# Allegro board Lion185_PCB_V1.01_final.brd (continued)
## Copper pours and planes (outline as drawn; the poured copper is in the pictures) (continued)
+VGFX on BOTTOM (solid shape): 83.86,87.98 84.45,87.98 84.73,87.7 85.2,87.7 85.2,87.69 85.22,87.69 85.22,87.63 85.93,87.63 85.93,87.69 85.96,87.69 85.96,87.7 87.39,87.7 87.41,87.69 87.43,87.68 87.55,87.57 87.56,87.55 87.56,87.52 87.56,87.37 87.56,87.34 87.55,87.32 87.36,87.13 87.36,86.65 87.24,86.52 86.72,86.52 86.61,86.63 86.61,87.03 86.58,87.07 86.35,87.07 86.35,87.18 85.6,87.18 85.6,87.18 84.78,87.18 84.78,86.99 84.74,86.94 84.74,86.84 84.65,86.75 84.65,86.57 83.76,86.57 83.76,86.5 83.74,86.45 83.64,86.43 83.64,86.32 83.63,86.32 83.63,85.55 83.64,85.55 83.64,83.46 83.62,83.42 83.58,83.4 83.19,83.4 83.14,83.42 83.12,83.46 83.12,84.65 83.13,84.65 83.13,85.42 83.12,85.42 83.12,86.13 82.9,86.35 82.88,86.4 82.89,86.44 82.9,86.92 82.43,87.03 82.4,87.02 82.36,87.04 82.34,87.08 82.34,87.63 83.02,88.31 83.52,88.31
+VGFX on LAY5 (solid shape): outline of 4668 points within 77.47,83.29 93.4,123.11
+VSDIO on BOTTOM (solid shape): 68.91,87.36 72.99,87.36 73,87.33 73.29,87.12 73.63,87.24 73.7,87.27 73.78,87.24 74.64,86.38 74.85,86.38 74.86,86.35 75.07,86.15 75.35,86.15 75.36,86.15 75.77,86.15 75.78,86.15 75.92,86.12 76.06,86.15 76.07,86.15 76.12,86.15 76.12,86.17 76.16,86.21 76.22,86.26 76.25,86.27 76.31,86.27 76.31,86.15 76.49,86.15 76.49,86.15 76.63,86.12 76.77,86.15 76.78,86.15 77.07,86.15 77.2,86.15 77.21,86.15 77.43,86.13 77.63,86.24 77.7,86.28 78.06,86.12 78.41,86.28 78.77,86.12 79.12,86.28 79.2,86.24 79.41,86.13 79.65,86.16 79.66,86.17 80.01,86.17 80.02,86.16 80.25,86.13 80.46,86.23 80.6,86.09 81.29,86.09 81.59,86.38 81.59,86.38 81.77,86.31 81.97,86.34 82,86.35 82.08,86.27 82.08,85.87 81.88,85.68 74.73,85.68 73.76,86.65 68.73,86.65 64.48,90.9 62.1,90.9 62.01,90.99 62.01,91.36 62.11,91.46 64.82,91.46
+VSFR on BOTTOM (solid shape): 87.7,118.77 87.7,118.01 87.53,117.85 87.53,116.13 87.41,116 86.78,116 86.61,116.17 86.61,118.74 86.69,118.83 87.64,118.83
+VSFR on LAY3 (solid shape): outline of 958 points within 84.7,81.13 93.36,106.21
+VSFR on LAY4 (solid shape): 89.21,106.54 89.21,105.76 88.2,104.75 88.2,102.42 86.68,100.89 86.68,97.67 86.3,97.29 86.3,90.78 86.14,90.45 86.34,90.14 86.39,90.07 86.37,89.98 85.06,88.68 84.88,88.68 84.55,89 84.54,89.06 84.52,89.12 84.52,89.56 84.52,89.57 84.55,89.72 84.52,89.87 84.52,89.88 84.52,90.11 84.62,90.21 84.65,90.22 84.69,90.21 85.15,90.15 85.33,90.58 85.33,98.28 85.62,98.58 86.1,98.81 85.9,99.29 85.87,99.31 85.87,101.16 87.12,102.42 87.12,105.24 88.56,106.67 89.08,106.67
+VSM on TOP (solid shape): 67.38,74.01 67.38,69.81 67.16,69.59 44.66,69.59 44.49,69.76 44.49,70.98 61.49,70.98 61.5,70.92 61.51,70.87 61.54,70.82 61.57,70.77 61.6,70.73 61.64,70.69 61.69,70.66 61.74,70.64 61.79,70.62 61.85,70.61 61.9,70.61 61.96,70.62 62.01,70.64 62.06,70.66 62.1,70.69 62.15,70.73 62.18,70.77 62.21,70.82 62.23,70.87 62.25,70.92 62.25,70.98 62.25,71.03 62.24,71.09 62.22,71.14 62.2,71.19 62.16,71.23 62.13,71.27 62.08,71.31 62.03,71.33 61.98,71.35 61.93,71.36 61.87,71.37 61.82,71.36 61.76,71.35 61.71,71.33 61.66,71.31 61.62,71.27 61.58,71.23 61.55,71.19 61.52,71.14 61.51,71.09 61.5,71.03 61.49,70.98 44.49,70.98 44.49,74.57 44.49,74.89 45.19,75.59 65.8,75.59
+VSM on TOP (solid shape): 99.58,59.8 99.58,59.72 99.57,59.7 99.54,59.29 99.89,59.09 99.91,59.09 100.17,58.83 100.17,58.53 100.15,58.53 100.15,58.5 100.08,58.5 100.08,57.58 99.67,57.58 99.67,58.5 99.6,58.5 99.6,58.53 98.35,58.53 98.35,58.5 98.28,58.5 98.28,57.58 97.87,57.58 97.87,58.5 97.8,58.5 97.8,58.53 97.72,58.53 97.72,58.77 98.04,59.09 98.06,59.09 98.42,59.3 98.36,59.72 98.36,59.73 98.34,59.77 98.49,59.93 99.46,59.93
+VSM on BOTTOM (solid shape): 98.31,58.83 98.31,58.54 97.9,58.13 96.77,58.13 96.32,58.58 96.32,58.88 96.47,59.02 98.12,59.02
+VSM on BOTTOM (solid shape): 88.72,58.99 89.12,58.99 89.29,58.82 89.29,58.45 89.07,58.23 87.22,58.23 87.04,58.42 87.04,58.85 87.17,58.99 87.57,58.99 87.77,59.19 88.51,59.19
+VSM on BOTTOM (solid shape): 89.28,56.11 89.28,55.88 89.09,55.69 88.66,55.69 88.49,55.52 87.84,55.52 87.63,55.73 87.18,55.73 87.05,55.86 87.05,56.1 87.24,56.29 89.1,56.29
+VSM on BOTTOM (solid shape): 98.32,56.13 98.32,55.88 98.15,55.7 97.75,55.7 97.55,55.5 96.79,55.5 96.6,55.69 96.22,55.69 96.08,55.84 96.08,56.12 96.39,56.43 98.02,56.43
+VSM on BOTTOM (solid shape): 87.69,121.9 87.69,120.24 87.62,120.17 86.28,120.17 86.12,120.01 86.02,120.01 85.76,120.27 85.76,121.83 85.94,122 87.6,122
+VSM on BOTTOM (solid shape): 129.45,55.14 129.45,51.3 129.12,50.97 127.61,50.97 126.87,51.71 126.87,51.78 128.16,53.08 128.16,55.14 128.23,55.21 129.38,55.21
+VSM on BOTTOM (solid shape): 90.49,59.58 90.49,59.27 90.67,59.09 91.12,59.09 91.31,59.28 92.19,59.28 92.41,59.05 93.1,59.05 93.24,59.19 93.96,59.19 94.1,59.05 94.58,59.05 94.72,58.91 94.72,58.61 94.43,58.32 90.47,58.32 89.81,58.98 89.81,59.59 89.92,59.71 90.37,59.71
+VSM on BOTTOM (solid shape): 101.69,53.54 101.69,50.12 101.38,49.81 88.53,49.81 87.97,50.37 85.13,50.37 84.96,50.54 84.96,50.67 85.14,50.85 85.34,50.85 85.58,51.1 85.58,51.39 85.74,51.54 86.37,51.54 86.45,51.46 86.45,51.12 86.71,50.87 87.19,50.87 87.4,51.07 87.4,51.27 87.47,51.34 88,51.34 88.46,50.88 88.97,50.88 89.28,51.19 89.95,51.19 90.33,50.81 92.72,50.81 92.82,50.9 92.82,51.14 92.92,51.24 93.57,51.24 93.96,50.86 96.18,50.86 96.28,50.86 96.37,50.95 96.37,51.28 96.46,51.37 96.99,51.37 97.52,50.85 99.73,50.85 100.12,51.23 100.5,51.23 100.94,51.67 100.94,53.51 101.13,53.7 101.53,53.7
+VSM on BOTTOM (solid shape): outline of 2522 points within 65.58,64.74 100.13,80.23
+VSM on LAY5 (solid shape): outline of 5880 points within 65.77,50.33 103.41,81.27
+VSM_VTT on BOTTOM (solid shape): 52.56,62.38 52.56,62.21 56.74,58.03 56.74,58.03 57.44,57.33 58.44,56.33 58.45,56.33 61.24,56.33 61.26,56.33 61.45,56.14 61.45,55.85 60.83,55.24 59.42,55.24 58.16,53.97 58.16,51.62 58.36,51.41 60.48,51.41 60.66,51.23 60.66,50.63 60.61,50.57 58.6,50.57 58.33,50.68 58.07,50.57 57.85,50.57 56.93,51.5 56.93,53.03 56.93,53.04 56.93,55.06 52.52,59.47 52.52,60.24 52.09,60.67 51.63,60.67 51.35,60.94 51.35,61.35 51.54,61.53 51.54,62.4 51.58,62.44 51.69,62.44 51.76,62.41 51.79,62.34 51.79,62.24 51.79,61.58 51.82,61.54 51.82,61.52 52.01,61.2 52.39,61.2 52.58,61.54 52.37,61.86 52.33,61.9 52.33,62.41 52.36,62.45 52.5,62.45
GL850_AVDD1 on BOTTOM (solid shape): 145.08,114.82 145.08,113.34 144.83,113.09 143.78,113.09 143.37,113.49 143.37,114.26 143.36,114.27 143.36,114.7 143.54,114.88 145.02,114.88
LAN_N1 on BOTTOM (solid shape): 62.78,18.95 62.78,13.55 62.53,13.3 61,13.3 60.79,13.51 60.79,18.78 61.15,19.13 62.6,19.13
LCD_VCC on TOP (solid shape): 50.56,135.33 50.56,132.12 49.95,131.51 46.52,131.51 46.28,131.27 46.28,129.55 46.16,129.43 45.17,129.43 45.17,129.42 43.29,129.42 43.05,129.66 43.05,132.35 42.94,132.46 41.73,132.46 41.6,132.59 41.6,135.5 41.91,135.81 50.08,135.81
LL1 on TOP (solid shape): outline of 112 points within 22.4,89.11 29,96.48
LL2 on TOP (solid shape): 29.19,81.66 29.19,71.4 28.71,70.91 25.37,70.91 24.37,71.91 24.37,77.16 24.37,77.16 24.37,78.84 24.37,78.84 24.37,81.33 24.86,81.82 29.03,81.82
REGOUT on BOTTOM (solid shape): 53.99,45.32 53.99,44.45 54.53,43.9 55.38,43.9 55.52,43.77 55.52,42.8 55.39,42.68 52.39,42.68 51.38,43.69 50.78,43.69 50.5,43.96 50.5,45.41 50.69,45.6 53.71,45.6
TP_VCC on TOP (solid shape): 11.47,39.74 11.47,38.42 11.2,38.15 10.55,38.15 9.98,37.58 6.52,37.58 6.4,37.7 6.4,39.18 6.58,39.37 8.19,39.37 8.82,40 11.22,40
N333289805 on TOP (solid shape): 131.61,67.88 131.61,64.73 131.49,64.6 129.35,64.6 128.93,64.19 128.93,62.87 128.77,62.71 126.02,62.71 125.54,63.19 125.54,66.7 125.86,66.7 125.86,66.65 125.88,66.6 125.9,66.55 125.93,66.5 125.96,66.46 126,66.42 126.05,66.39 126.1,66.36 126.15,66.35 126.21,66.34 126.26,66.34 126.32,66.35 126.37,66.36 126.42,66.39 126.47,66.42 126.51,66.46 126.54,66.5 126.57,66.55 126.59,66.6 126.61,66.65 126.61,66.7 126.61,66.76 126.6,66.81 126.58,66.87 126.56,66.92 126.52,66.96 126.49,67 126.44,67.03 126.39,67.06 126.34,67.08 126.29,67.09 126.23,67.1 126.18,67.09 126.12,67.08 126.07,67.06 126.02,67.03 125.98,67 125.94,66.96 125.91,66.92 125.89,66.87 125.87,66.81 125.86,66.76 125.86,66.7 125.54,66.7 125.54,67.82 125.88,68.15 131.34,68.15
N350299694 on TOP (solid shape): 48.84,81.96 48.84,76.5 48.37,76.03 39.31,76.03 38.69,76.66 38.69,81.39 39.59,82.3 48.5,82.3
N370571694 on LAY3 (solid shape): 88.91,83.94 88.91,83.38 88.7,83.16 88.37,83.16 88.35,83.18 87.89,83.22 87.73,82.79 87.45,82.52 87.34,82.52 87.04,82.82 87.04,82.98 87.33,83.27 87.58,83.38 87.69,83.64 88.08,84.03 88.22,84.05 88.34,84.12 88.72,84.12
N370574162 on BOTTOM (solid shape): 73,85.39 73.28,85.17 73.62,85.28 73.65,85.32 74.41,84.56 74.83,84.56 74.94,84.45 78.47,84.45 78.61,84.31 78.81,84.27 78.87,84.26 78.91,84.22 79.68,84.22 79.68,84.45 79.88,84.45 79.88,84.22 80.63,84.22 80.63,84.32 81.45,84.32 81.46,84.29 81.77,84.03 82.13,84.2 82.15,84.22 82.27,84.22 82.5,84.05 82.78,84.08 82.82,84.09 82.87,84.04 82.87,83.61 82.67,83.41 82.38,83.41 82.17,83.63 81.31,83.63 81.28,83.65 81.27,83.7 81.26,83.74 81.2,83.74 81.19,83.76 80.9,83.93 80.61,83.76 80.6,83.74 80.49,83.74 80.48,83.76 80.31,83.91 80.08,83.91 80.05,83.9 79.96,83.84 79.9,83.76 79.89,83.74 79.07,83.74 79.05,83.76 78.77,83.93 78.48,83.76 78.47,83.74 75.51,83.74 75.5,83.76 75.21,83.93 74.92,83.76 74.91,83.74 74.08,83.74 73.04,84.78 68.71,84.78 68.59,84.89 68.59,85.23 68.79,85.42 72.98,85.42
N370574202 on BOTTOM (solid shape): 68.63,86.39 73.66,86.39 74.63,85.42 81.99,85.42 82.33,85.77 82.33,86.06 82.47,86.2 82.76,86.2 82.9,86.05 82.9,85.13 82.6,84.83 81.74,84.83 81.73,84.83 80.63,84.83 80.63,84.93 79.88,84.93 79.88,84.82 79.68,84.82 79.68,84.93 78.93,84.93 78.93,84.91 78.87,84.91 78.86,84.91 78.68,84.91 78.52,84.82 74.51,84.82 73.72,85.61 73.72,85.62 73.4,85.93 73.01,85.73 68.68,85.73 65.5,88.91 62.98,88.91 62.79,89.1 62.79,89.47 62.9,89.57 65.45,89.57
N370574265 on BOTTOM (solid shape): outline of 1089 points within 89.37,85.44 108.15,95.97
N370574283 on BOTTOM (solid shape): 86.84,98.71 86.84,97.38 86.78,97.32 86.47,97.32 86.47,97.05 86.2,97.05 86.2,96.3 86.25,96.3 86.25,95.67 86.39,95.53 86.43,95.47 86.47,95.42 86.47,95.18 86.37,94.97 86.43,94.75 86.44,94.74 86.44,94.65 86.34,94.65 86.34,93.89 86.47,93.89 86.47,93.7 86.34,93.7 86.34,92.94 86.38,92.94 86.37,92.88 86.38,92.72 86.47,92.58 86.47,91.71 86.82,91.36 86.82,89.66 86.7,89.55 86.26,89.55 86,89.81 86,91.23 85.71,91.53 85.71,98.32 86.16,98.76 86.79,98.76
N370574303 on BOTTOM (solid shape): 91.04,105.84 89.61,104.41 89.61,100.7 89.57,100.69 89.43,100.63 89.34,100.52 89.31,100.28 89.45,100.09 89.49,100.01 89.45,99.93 89.3,99.66 89.45,99.38 89.49,99.3 89.45,99.22 89.4,99.18 89.35,99.12 89.33,99.09 89.31,99.04 88.41,98.13 88.41,95.85 88.35,95.66 88.41,95.47 88.41,91.07 88.49,90.99 88.49,90.31 88.71,90.09 89.14,90.09 89.14,89.53 89.01,89.39 88.65,89.39 88.64,89.4 88.64,89.64 88.43,89.85 88.02,89.85 87.83,90.04 87.83,91.1 88.01,91.39 87.83,91.69 87.83,91.81 87.98,91.96 88,92.18 88,92.24 88.04,92.24 88.04,92.99 87.83,92.99 87.83,93.19 88.04,93.19 88.04,93.94 87.94,93.94 87.94,94.03 87.95,94.04 88,94.31 87.83,94.53 87.83,96.07 88.01,96.37 87.83,96.66 87.83,96.79 88.01,97.08 87.83,97.37 87.83,97.43 87.79,97.45 87.75,97.46 87.75,98.37 88.99,99.62 88.99,99.64 89.01,99.68 89.05,99.84 88.99,100.01 88.99,104.82 90.53,106.35
N370827950 on TOP (solid shape): 132.89,105.85 132.89,102.15 132.43,101.68 127.53,101.68 126.09,103.12 121.38,103.12 121.24,103.26 121.24,105.83 121.45,106.05 132.69,106.05
N371193330 on BOTTOM (solid shape): 145,97.24 145,94.26 144.64,93.9 143.34,93.9 143.17,94.07 143.17,95.99 143.29,96.12 143.29,97.43 143.51,97.65 144.59,97.65
N371829343 on TOP (solid shape): 95.67,124.58 95.67,123.69 95.5,123.52 94.06,123.52 93.76,123.82 93.76,124.58 93.88,124.7 95.55,124.7
N371829347 on TOP (solid shape): 102.04,130.62 102.04,123.28 101.38,122.63 101.38,117.51 101.64,117.25 101.64,116.15 101.45,115.96 101.45,115.31 101.39,115.25 101.26,115.25 101.19,115.33 101.19,116 101,116.18 101,116.47 100.22,117.26 99.97,117.26 99.87,117.15 99.87,116.5 99.66,116.29 98.82,116.29 98.6,116.51 98.6,118.03 98.6,118.03 98.6,122.74 98.6,122.74 97.92,123.42 96.38,123.42 96.21,123.59 96.21,131.15 96.44,131.38 101.28,131.38
N373532752 on TOP (solid shape): 104.59,22.84 104.59,21.35 105.81,20.12 105.81,17.05 105.46,16.7 101.31,16.7 101.11,16.9 101.11,19.2 99.54,20.77 99.54,22.33 100.59,23.37 104.06,23.37
N373532763 on TOP (solid shape): 99.15,21.74 99.15,20.88 100.75,19.29 100.75,15.09 100.45,14.78 97.18,14.78 96.79,15.17 96.79,18.21 95.19,19.81 95.19,21.66 95.74,22.22 98.68,22.22
N373533528 on TOP (solid shape): 105.75,11.81 105.75,9.53 105.6,9.38 104.3,9.38 104.14,9.54 104.14,11.78 104.29,11.92 105.63,11.92
N373549786 on TOP (solid shape): outline of 125 points within 13.24,26.25 27.68,39.12
N373549823 on TOP (solid shape): 20.67,24.64 20.67,21.59 20.18,21.1 13.38,21.1 12.99,21.49 12.99,26.24 13.47,26.72 18.59,26.72
N373549823 on BOTTOM (solid shape): 23.02,26.91 23.02,23.35 22.6,22.93 16.34,22.93 16.11,23.16 16.11,25.94 16.32,26.15 18.84,26.15 18.87,26.18 18.87,26.19 19.23,26.55 19.23,27.14 19.48,27.39 19.48,27.4 22.53,27.4
N373561472 on BOTTOM (solid shape): 60.83,113.98 60.83,113.78 62.24,112.37 63.7,112.37 63.78,112.3 63.78,110.87 63.65,110.75 60.51,110.75 60.3,110.96 60.3,112.72 59.93,113.1 59.93,113.99 60.08,114.15 60.66,114.15
N373765744 on TOP (solid shape): 7.86,111.3 7.86,109.65 7.65,109.44 5.15,109.44 5,109.59 5,111.34 5.14,111.47 7.69,111.47
N373783458 on TOP (solid shape): 13.43,44.74 13.43,42.44 13.34,42.35 12.51,42.35 11.53,41.37 11.53,40.96 11.43,40.87 8.84,40.87 8.68,41.02 8.68,42.21 8.81,42.34 11.09,42.34 11.43,42.68 11.43,44.68 11.62,44.87 13.3,44.87
N373800615 on BOTTOM (solid shape): 6.37,16.22 6.37,12.9 6.11,12.64 3.92,12.64 3.78,12.77 3.78,16.2 4.06,16.48 6.11,16.48
N373937554 on TOP (solid shape): 45.48,128.13 46.16,128.13 46.27,128.01 46.27,127.4 46.16,127.28 46.16,126.25 45.95,126.04 44.05,126.04 43.96,125.94 43.96,125.39 43.68,125.11 42.67,125.11 42.5,125.29 42.5,128.08 42.78,128.36 45.25,128.36

Small or netless copper shapes (teardrops, artwork), in the pictures only: 4 on TOP, 5 on BOTTOM

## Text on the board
Ref Des/Silkscreen Bottom: BA | BF | BOTTOM | BB | BD | BC | BE | REF
Ref Des/Silkscreen Top: 5000-0004-6901 | 2014.0505.1700 | TOP | V1.01 | TD | UM1B_MAIN_PCB | U1 | TA | TB | TE | TC | REF
User.20: FIGURE | SIZE | 9.84 | 15.75 | 27.56 | 31.5 | 35.43 | 51.18 | 133.86 | 142.0 | 149.61 | 157.48 | 43.31 | 47.24 | 62.99 | 78.74 | 94.49 | 314.96 | 43.31x23.62 | 47.24x19.69 | 78.74x31.5 | 90.55x23.62 | 94.49x27.56 | 102.36x27.56 | DRILL CHART: TOP to BOTTOM | ALL UNITS ARE IN MILS | PLATED | NON-PLATED | QTY | 2712 | 40 | 679 | 9 | 2 | 8 | 4 | 1 | 10 | 3
